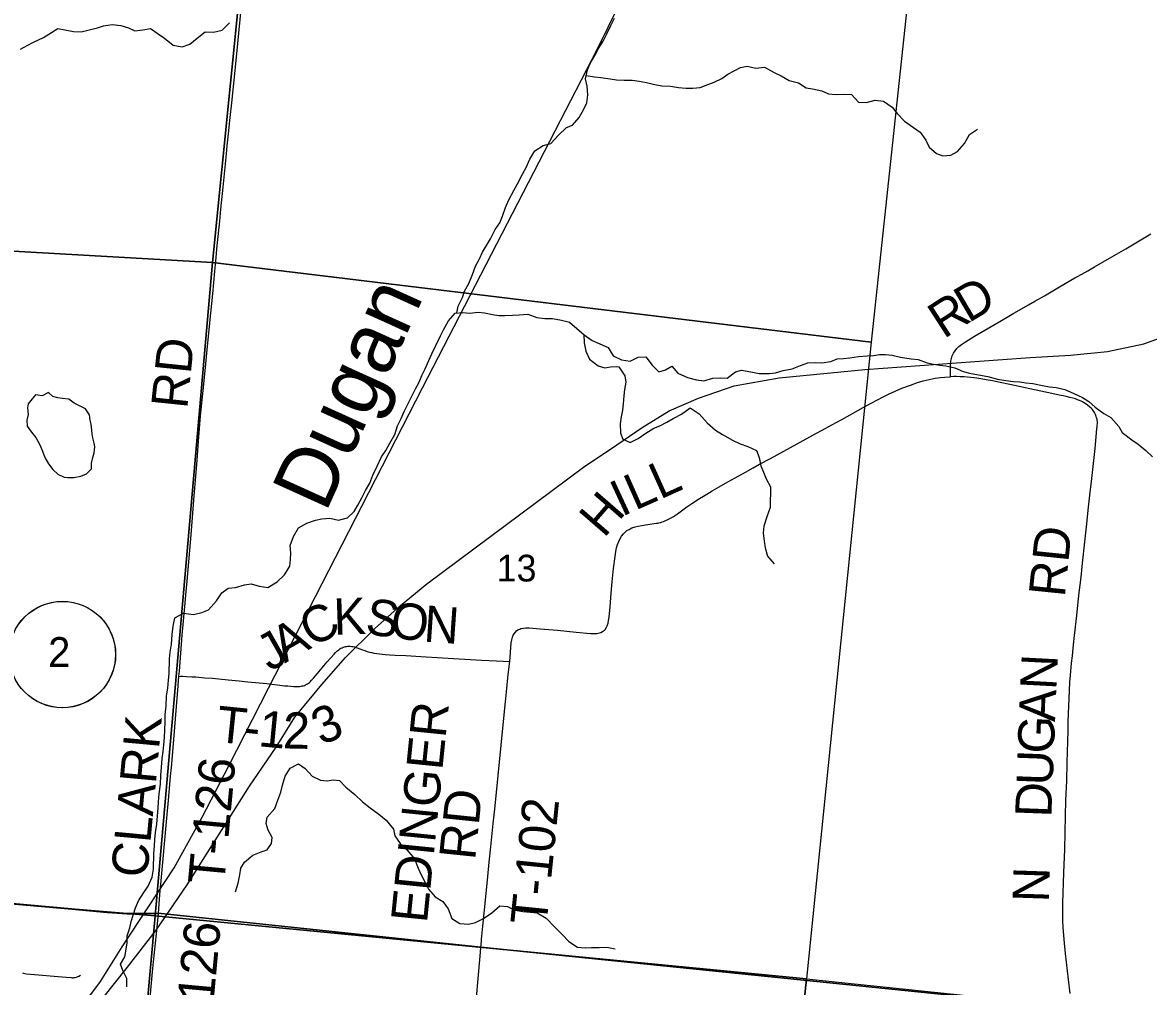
# Model space of a CAD drawing. Extents: x 0 to 1067, y 0 to 440.
# Drawn here: x 403.1 to 508.9, y 167.1 to 257.7 of the extents above; entities that cross this region are included whole.
import ezdxf

# ---------------------------------------------------------------- set-up
doc = ezdxf.new("R2010")
doc.units = 0
for name, color, linetype in [('GM_X_City_Street', 7, 'Continuous'), ('GM_X_Minor_Lake', 7, 'Continuous'), ('GM_X_Minor_River', 7, 'Continuous'), ('GM_X_Minor_River_Text', 7, 'Continuous'), ('GM_X_Rail_Line', 7, 'Continuous'), ('GM_X_Section', 7, 'Continuous'), ('GM_X_Section_Text', 7, 'Continuous'), ('GM_X_Township_Road', 7, 'Continuous'), ('GM_X_Township_Road_Text', 7, 'Continuous'), ('SH_Masking', 7, 'Continuous'), ('SH_Text', 7, 'Continuous')]:
    doc.layers.add(name, color=color, linetype=linetype)

msp = doc.modelspace()

# ---------------------------------------------------------------- linework, layer by layer
at = {"layer": 'GM_X_City_Street'}
msp.add_lwpolyline([(403.08, 168.37), (403.17, 168.35), (403.3, 168.31), (403.45, 168.29), (407.17, 167.97), (407.64, 167.93), (407.76, 167.92), (407.83, 167.92), (407.9, 167.93), (407.98, 167.94), (408.04, 167.95), (408.15, 167.98), (408.27, 168.02), (408.36, 168.05), (408.53, 168.15)], dxfattribs=at)
at = {"layer": 'GM_X_Minor_Lake'}
for points in [[(409.36, 215.55), (409.56, 215.75), (409.57, 216.27), (409.69, 216.79), (409.81, 217.25), (409.89, 217.79), (409.82, 218.14), (409.69, 218.66), (409.63, 219.03), (409.61, 219.37), (409.53, 219.94), (409.44, 220.31), (409.36, 220.81), (409, 221.36), (408.44, 221.64), (407.94, 221.9), (407.42, 222.29), (406.85, 222.33), (406.4, 222.4), (405.94, 222.52), (405.52, 222.91), (404.94, 222.58), (404.31, 222.7), (403.98, 222.32), (403.61, 221.84)], [(403.61, 221.84), (403.56, 221.46), (403.62, 220.84), (403.5, 220.3), (403.51, 219.75), (403.92, 219.17), (404.32, 218.67), (404.72, 218), (404.96, 217.38), (405.18, 216.81), (405.51, 216.21), (405.94, 215.68), (406.41, 215.24), (406.98, 214.96), (407.34, 214.91), (407.89, 214.93), (408.55, 215.05), (409.1, 215.27), (409.36, 215.55)]]:
    msp.add_lwpolyline(points, dxfattribs=at)
at = {"layer": 'GM_X_Minor_River'}
for points in [[(402.9, 255.18), (403.52, 255.51), (404.12, 255.82), (405.04, 256.26), (405.79, 256.73), (406.39, 257.11), (407.07, 256.99), (407.87, 256.82), (408.6, 256.81), (409.47, 257.02), (410.13, 257.17), (410.7, 257.37), (411.52, 257.5), (412.32, 257.4), (413.04, 257.16), (413.63, 256.9), (414.39, 257), (415.12, 257.11), (415.82, 256.6), (416.42, 256.2), (417.24, 255.53), (418.08, 255.38), (418.81, 255.64), (419.5, 256.2), (420.24, 256.79), (421.03, 256.78), (421.83, 256.95), (422.55, 257.64)], [(443.91, 230.38), (444.04, 231.03), (444.42, 231.82), (444.63, 232.43), (445.03, 233.16), (445.36, 233.99), (445.66, 234.77), (446.02, 235.47), (446.3, 236.08), (446.7, 236.73), (447.07, 237.34), (447.51, 238.23), (447.93, 238.84), (448.19, 239.49), (448.48, 240.29), (448.78, 241.01), (449.25, 241.9), (449.6, 242.51), (450.09, 243.43), (450.42, 244.05), (450.75, 244.82), (451.24, 245.61), (452.02, 246.12), (452.75, 246.29), (453.47, 247.1), (454.21, 247.82), (454.78, 248.02), (455.39, 248.74), (455.83, 249.53), (456.11, 250.12), (456.21, 250.89), (456.16, 251.69), (456.01, 252.38), (456.18, 253.24), (456.42, 253.83), (456.86, 254.56), (457.21, 255.23), (457.65, 255.91), (458, 256.61), (458.38, 257.38), (458.73, 258.08)], [(456.07, 252.69), (456.83, 252.57), (457.44, 252.52), (458.31, 252.37), (458.92, 252.29), (459.63, 252.26), (460.38, 252.25), (461.04, 252.15), (461.74, 252.03), (462.36, 251.88), (463.17, 251.73), (463.99, 251.68), (464.74, 251.58), (465.45, 251.5), (466.09, 251.51), (466.77, 251.57), (467.34, 251.79), (468.08, 252.08), (468.81, 252.41), (469.38, 252.81), (469.98, 253.12), (470.56, 253.46), (471.2, 253.58), (472.01, 253.37), (472.81, 253.49), (473.72, 252.98), (474.39, 252.67), (475.14, 252.23), (476.03, 252.01), (476.75, 251.53), (477.34, 251.43), (478.22, 251.25), (478.84, 250.97), (479.56, 250.92), (480.36, 250.95), (481, 250.9), (481.65, 250.18), (482.42, 250.15), (483.22, 250.39), (484.02, 250.29), (484.81, 249.73), (485.28, 249.13), (485.97, 248.41), (486.83, 247.81), (487.44, 247.37), (487.98, 246.61), (488.31, 245.97), (488.98, 245.36), (489.57, 245.15), (490.32, 245.21), (490.97, 245.56), (491.62, 246.31), (492.08, 247.14), (492.84, 247.64)], [(412.91, 171.16), (412.92, 171.85), (413.16, 172.6), (413.28, 173.21), (413.52, 173.89), (413.71, 174.48), (413.97, 175.14), (414.48, 175.91), (414.88, 176.52), (415.28, 177.38), (415.4, 178.13), (415.42, 179.59), (415.48, 180.32), (415.51, 180.89), (415.59, 181.55), (415.69, 182.34), (415.77, 183.14), (415.83, 183.84), (415.86, 184.46), (415.91, 185.21), (416.04, 186.1), (416.08, 186.92), (416.13, 187.69), (416.21, 188.53), (416.31, 189.17), (416.37, 189.81), (416.42, 190.49), (416.46, 191.2), (416.49, 191.93), (416.5, 192.63), (416.58, 193.48), (416.61, 194.39), (416.74, 195.14), (416.8, 195.89), (416.87, 196.46), (416.89, 197.87), (416.97, 198.51), (417.09, 199.26), (417.15, 200.17), (417.23, 200.94), (417.4, 201.74), (418.21, 202.16), (419.14, 202.06), (419.92, 202.23), (420.56, 202.49), (421.32, 203.33), (421.81, 204.09), (422.41, 204.52), (423.09, 204.6), (423.94, 204.82), (424.58, 204.94), (425.33, 204.71), (426.15, 204.58), (427, 205.12), (427.69, 205.77), (428.22, 206.6), (428.28, 207.22), (428.29, 207.81), (428.25, 208.52), (428.56, 209.38), (429.03, 210.19), (429.81, 210.62), (430.61, 210.9), (431.2, 211.05), (431.98, 211.11), (432.77, 210.9), (433.64, 211.13), (434.24, 211.72), (434.59, 212.33), (434.99, 213.08), (435.32, 213.69), (435.74, 214.39), (436, 215.14), (436.42, 216), (436.82, 216.86), (437.22, 217.47), (437.59, 218.15), (438.08, 218.96), (438.34, 219.78), (438.67, 220.48), (438.96, 221.11), (439.26, 221.75), (439.68, 222.56), (440.03, 223.26), (440.36, 223.88), (440.62, 224.49), (440.93, 225.14), (441.26, 225.91), (441.56, 226.55), (441.94, 227.32), (442.38, 228.22), (442.64, 228.81), (443.11, 229.63), (443.73, 230.37), (444.46, 230.43), (445.1, 230.35), (445.92, 230.45), (446.49, 230.4), (447.24, 230.25), (447.85, 230.13), (448.42, 230.15)], [(448.42, 230.15), (449.15, 230.18), (449.77, 230.22), (450.59, 230.28), (451.41, 229.97), (452.18, 229.85), (452.88, 229.86), (453.75, 229.69), (454.5, 229.52), (455.19, 228.92), (455.87, 228.34), (456.61, 227.8), (457.34, 227.47), (458.13, 227.14), (458.6, 226.34), (459.39, 225.99), (460.18, 225.84), (460.94, 226.24), (461.67, 226.25), (462.25, 225.47), (462.9, 224.84), (463.52, 225.04), (464.1, 225.37), (464.68, 224.71), (465.58, 224.33), (466.42, 224.09), (467.11, 224.01), (467.95, 224.25), (468.73, 224.29), (469.3, 224.26), (470.08, 224.86), (470.65, 225.01), (471.54, 224.86), (472.33, 224.69), (473.29, 224.7), (473.86, 224.76), (474.59, 224.96), (475.41, 225.13), (476.19, 225.46), (476.9, 225.7), (477.59, 225.74), (478.22, 225.68), (479.07, 225.83), (479.64, 226.07), (480.26, 226.11), (480.83, 226.17), (481.65, 226.3), (482.49, 226.35), (483.06, 226.39), (483.63, 226.48), (484.2, 226.49), (484.82, 226.41), (485.61, 226.22), (486.61, 226.07), (487.27, 226.02), (488.11, 225.68), (488.72, 225.56), (489.31, 225.49), (489.88, 225.41), (490.7, 225.24), (491.49, 224.89), (492.08, 224.74), (492.92, 224.57), (493.81, 224.4), (494.72, 224.16), (495.49, 224.03), (496.24, 223.95), (496.81, 223.9), (497.4, 223.82), (498.04, 223.75), (498.95, 223.58), (499.6, 223.43), (500.22, 223.38), (501.06, 223.2), (501.83, 222.85), (502.71, 222.43), (503.3, 222.06), (503.91, 221.52), (504.72, 220.94), (505.37, 220.55), (506.13, 219.72), (506.45, 219.14), (507.35, 218.45), (507.93, 218.05), (508.65, 217.45), (509.28, 216.85)], [(455.85, 228.36), (455.86, 227.58), (456.03, 226.78), (456.36, 226.05), (457.19, 225.4), (457.81, 225.23), (458.52, 225.36), (459.13, 225.31), (459.69, 224.48), (459.79, 223.88), (459.65, 223.18), (459.61, 222.59), (459.54, 221.84), (459.46, 221.24), (459.34, 220.61), (459.26, 219.95), (459.29, 219.1), (459.51, 218.51), (460.21, 218.2), (460.95, 218.6), (461.68, 219.09), (462.42, 219.56), (462.99, 219.78), (463.63, 220.12), (464.23, 220.45), (465.03, 220.87), (465.84, 221.48), (466.67, 220.9), (467.44, 220.06), (468.2, 219.37), (468.88, 218.97), (469.81, 218.44), (470.53, 218.08), (471.26, 217.82), (472.07, 217.45), (472.33, 216.81), (472.48, 216.01), (472.72, 215.41), (472.99, 214.81), (473.37, 214.03), (473.38, 213.44), (473.35, 212.74), (473.36, 212.1), (473.03, 211.21), (472.77, 210.35), (472.69, 209.71), (472.79, 208.94), (472.87, 208.32), (473.09, 207.54), (473.74, 206.8)], [(423.1, 176), (423.36, 176.79), (423.51, 177.59), (423.61, 178.2), (423.96, 178.79), (424.74, 179.42), (425.5, 179.75), (426.07, 179.94), (426.49, 180.53), (426.54, 181.1), (426.18, 181.79), (425.97, 182.41), (426.09, 183), (426.81, 183.81), (427.07, 184.6), (427.37, 185.35), (427.52, 186.01), (427.76, 186.85), (428.23, 187.6), (429.01, 188), (429.66, 187.58), (430.31, 186.86), (431.08, 186.49), (431.7, 186.43), (432.29, 186.51), (432.88, 186.44), (433.46, 185.82), (434.3, 185.14), (435.02, 184.45), (435.76, 183.87), (436.57, 183.29), (437.27, 182.71), (437.96, 181.88), (438.07, 181.26), (438.58, 180.53), (439.23, 179.9), (439.93, 179.09), (440.28, 178.22), (440.54, 177.6), (440.94, 176.87), (441.25, 176.23), (441.86, 175.51), (442.6, 175.07), (443.1, 174.38), (443.42, 173.49), (444.19, 173.02), (445.01, 172.96), (445.65, 173.11), (446.41, 173.47), (447.19, 174.03), (447.93, 174.68), (448.66, 174.6), (449.38, 174.27), (450.11, 174.15), (450.81, 174.09), (451.45, 174.01), (452.29, 173.5), (453.16, 172.65), (453.79, 171.98), (454.44, 171.31), (455.25, 170.79), (455.98, 170.72), (456.55, 170.75), (457.28, 170.77), (457.99, 170.78), (458.78, 170.63)], [(412.89, 167.06), (412.87, 167.85), (412.5, 168.61), (412.3, 169.18), (412.69, 169.88), (412.91, 171.16)]]:
    msp.add_lwpolyline(points, dxfattribs=at)
at = {"layer": 'GM_X_Rail_Line'}
for points in [[(408.56, 165.1), (410.41, 167.56), (412.44, 170.81), (417.32, 178.23), (419.98, 182.99), (422.46, 187.82), (426.2, 195.11), (440.66, 223.35), (457.12, 255.21), (463.1, 267.38), (466.12, 273.22), (468.95, 277.71), (472.1, 282.34), (474.93, 286.23), (477.92, 290.37), (491.28, 306.36), (506.27, 324.25), (534.38, 357.19), (539, 362.72)], [(409.52, 164.62), (412.95, 168.92), (415.65, 172.39), (418.55, 176.66), (424.42, 185.93), (426.91, 189.58), (428.68, 192.4), (431.2, 195.48), (433.45, 198.02), (436.16, 200.71), (438.6, 202.89), (441.08, 204.93), (455.8, 215.89), (458.95, 218), (461.32, 219.62), (463.86, 221.17), (466.61, 222.36), (469.96, 223.52), (474.2, 224.3), (482.24, 225.06), (492.58, 225.83), (497.8, 226.21), (501.58, 226.41), (505.06, 226.77), (508.48, 227.47), (511.67, 228.63)]]:
    msp.add_lwpolyline(points, dxfattribs=at)
at = {"layer": 'GM_X_Section'}
for points in [[(365.53, 299.9), (426.84, 293.81), (420.94, 235.13), (359.76, 238.61)], [(489.23, 287.4), (482.85, 227.63), (420.94, 235.13), (426.84, 293.81)], [(359.76, 238.61), (420.94, 235.13), (415.56, 173.73), (353.18, 178.94)], [(482.85, 227.63), (476.78, 167.81), (415.56, 173.73), (420.94, 235.13)], [(353.18, 178.94), (415.56, 173.73), (410.18, 114.4), (348.26, 119.58)], [(476.78, 167.81), (470.49, 107.7), (410.18, 114.4), (415.56, 173.73)], [(537.23, 161.53), (531.15, 101.7), (501.28, 103.8), (470.49, 107.7), (476.78, 167.81)]]:
    msp.add_lwpolyline(points, close=True, dxfattribs=at)
at = {"layer": 'GM_X_Township_Road'}
for points in [[(421.25, 235.26), (421.39, 236.71), (421.62, 239), (421.73, 240.12), (421.94, 242.2), (422.24, 245.32), (422.32, 246.1), (422.44, 247.21), (422.61, 248.76), (422.76, 250.13), (422.89, 251.36), (423.07, 253.18), (423.31, 255.7), (423.63, 258.93)], [(490.29, 224.39), (490.29, 225.28), (490.3, 225.55), (490.34, 225.85), (490.4, 226.11), (490.47, 226.36), (490.58, 226.61), (490.73, 226.83), (490.9, 227.04), (491.1, 227.22), (491.33, 227.42), (491.7, 227.67), (492.56, 228.2), (495.11, 229.67), (495.79, 230.07), (496.27, 230.35), (497.65, 231.16), (498.24, 231.48), (499.14, 232), (500.72, 232.92), (502, 233.68), (502.19, 233.79), (502.65, 234.04), (503.2, 234.35), (503.85, 234.71), (505.46, 235.65), (506.78, 236.42), (507.87, 237.06), (509.12, 237.81)], [(417.78, 196.23), (417.82, 196.73), (417.96, 198.41), (418.1, 200.11), (418.34, 202.79), (418.47, 204.22), (418.56, 205.19), (418.65, 206.27), (418.92, 209.54), (419.22, 213.21), (419.37, 215.02), (419.49, 216.56), (419.63, 218.35), (419.82, 220.7), (420.07, 223.09), (420.26, 224.95), (420.48, 227.25), (420.79, 230.36), (420.96, 232.18), (421.16, 234.3), (421.25, 235.26)], [(448.87, 197.63), (448.95, 198.47), (449.02, 199.37), (449.07, 199.67), (449.13, 199.93), (449.21, 200.11), (449.29, 200.24), (449.41, 200.4), (449.52, 200.5), (449.65, 200.6), (449.82, 200.68), (449.93, 200.72), (450.16, 200.77), (450.39, 200.79), (450.69, 200.78), (451.73, 200.7), (453.37, 200.56), (455.11, 200.39), (456.48, 200.27), (456.78, 200.25), (457.07, 200.26), (457.32, 200.31), (457.45, 200.36), (457.6, 200.45), (457.77, 200.58), (457.84, 200.65), (457.98, 200.86), (458.04, 200.99), (458.12, 201.23), (458.17, 201.48), (458.21, 201.81), (458.31, 202.77), (458.42, 204.04), (458.51, 205.11), (458.64, 206.38), (458.77, 207.49), (458.84, 207.97), (458.91, 208.3), (459.01, 208.63), (459.12, 208.91), (459.25, 209.19), (459.39, 209.41), (459.56, 209.62), (459.71, 209.79), (459.89, 209.93), (460.09, 210.05), (460.36, 210.18), (460.68, 210.3), (460.94, 210.36), (461.64, 210.47), (462.67, 210.62), (462.81, 210.64), (462.88, 210.65), (463.01, 210.68), (463.08, 210.7), (463.21, 210.75), (463.34, 210.79), (463.67, 210.93), (464, 211.09), (464.28, 211.27), (464.64, 211.52), (464.88, 211.7), (465.51, 212.16), (465.98, 212.48), (466.7, 212.94), (467.08, 213.17), (467.4, 213.36), (467.91, 213.67), (468.55, 214.05), (469.36, 214.52), (470.05, 214.89), (471.02, 215.43), (471.74, 215.82), (472.36, 216.16), (473.37, 216.71), (474.65, 217.4), (475.9, 218.07), (477.65, 219.05), (478.25, 219.37), (479.16, 219.86), (480.08, 220.37), (481.37, 221.1), (482.32, 221.62), (483.97, 222.49), (484.47, 222.74), (485.74, 223.3), (486.54, 223.61), (487.21, 223.84), (487.75, 224), (488.3, 224.13), (488.85, 224.24), (489.37, 224.31), (489.77, 224.35), (490.29, 224.39)], [(501.54, 166.42), (501.38, 167.76), (501.11, 170.2), (501.02, 171.17), (500.95, 171.87), (500.89, 172.66), (500.86, 173.25), (500.85, 173.89), (500.86, 174.93), (500.96, 177.8), (501.01, 179.26), (501.04, 179.96), (501.09, 181.6), (501.11, 183.09), (501.15, 184.59), (501.23, 186.41), (501.27, 188.12), (501.3, 189.17), (501.32, 190.06), (501.35, 191.18), (501.37, 191.96), (501.39, 192.74), (501.45, 194.16), (501.53, 195.68), (501.58, 196.35), (501.68, 197.47), (501.76, 198.17), (501.87, 199.21), (501.96, 200.06), (502.17, 201.95), (502.28, 202.91), (502.41, 204.1), (502.57, 205.55), (502.71, 206.88), (502.93, 208.88), (503.08, 210.29), (503.27, 212.14), (503.4, 213.25), (503.55, 214.55), (503.89, 217.66), (504.07, 219.48), (504.09, 219.7), (504.1, 219.84), (504.11, 219.96), (504.11, 220.07), (504.11, 220.13), (504.11, 220.19), (504.1, 220.25), (504.09, 220.32), (504.08, 220.38), (504.06, 220.45), (504.03, 220.54), (504, 220.64), (503.92, 220.84), (503.83, 221.04), (503.7, 221.22), (503.61, 221.33), (503.51, 221.43), (503.39, 221.54), (503.17, 221.73), (503.06, 221.8), (502.81, 221.96), (502.71, 222.02), (502.59, 222.09), (502.43, 222.16), (502.24, 222.23), (502.04, 222.3), (501.79, 222.37), (501.52, 222.44), (501.18, 222.52), (500.88, 222.58), (500.51, 222.66), (499.83, 222.81), (497.76, 223.25), (496.76, 223.46), (495.89, 223.65), (494.97, 223.84), (494.25, 223.99), (493.65, 224.1), (493.17, 224.18), (492.77, 224.25), (492.23, 224.32), (491.86, 224.35), (491.58, 224.37), (491.22, 224.39), (490.87, 224.4), (490.61, 224.4), (490.29, 224.39)], [(417.78, 196.23), (417.94, 196.24), (418.14, 196.24), (418.49, 196.23), (418.98, 196.2), (419.38, 196.18), (420.22, 196.11), (420.95, 196.05), (422.41, 195.9), (423.45, 195.8), (424.27, 195.73), (426.05, 195.55), (427.72, 195.36), (428.01, 195.34), (428.31, 195.31), (428.58, 195.29), (428.79, 195.28), (428.92, 195.28), (429.04, 195.28), (429.16, 195.29), (429.26, 195.31), (429.37, 195.33), (429.48, 195.36), (429.58, 195.39), (429.67, 195.43), (429.78, 195.49), (429.86, 195.54), (429.96, 195.6), (430.04, 195.66), (430.14, 195.76), (430.22, 195.84), (430.42, 196.07), (430.61, 196.28), (431.72, 197.6), (432.36, 198.32), (432.51, 198.48), (432.63, 198.59), (432.72, 198.67), (432.81, 198.74), (432.9, 198.81), (433, 198.87), (433.11, 198.92), (433.21, 198.97), (433.33, 199.01), (433.44, 199.03), (433.55, 199.05), (433.66, 199.06), (433.76, 199.07), (433.89, 199.07), (434.01, 199.05), (434.08, 199.05), (434.15, 199.03), (434.27, 199), (434.52, 198.91), (434.77, 198.82), (435.04, 198.72), (435.26, 198.65), (435.46, 198.58), (435.68, 198.52), (435.9, 198.47), (436.11, 198.42), (436.39, 198.38), (436.66, 198.34), (436.88, 198.31), (437.18, 198.29), (437.61, 198.26), (438.11, 198.23), (439.12, 198.18), (440.53, 198.11), (442.54, 197.98), (446.22, 197.75), (447.63, 197.68), (448.87, 197.63)], [(446.23, 171.52), (446.35, 172.75), (446.47, 173.97), (446.63, 175.53), (446.81, 177.42), (446.95, 178.79), (447.11, 180.23), (447.33, 182.42), (447.46, 183.76), (447.79, 186.91), (448.36, 192.62), (448.48, 193.84), (448.57, 194.77), (448.74, 196.4), (448.87, 197.63)], [(415.85, 173.95), (416, 175.74), (416.1, 177.03), (416.6, 182.55), (416.82, 184.96), (417, 186.85), (417.08, 187.67), (417.23, 189.52), (417.46, 192.24), (417.68, 194.95), (417.78, 196.23)], [(400.34, 175.05), (407.69, 174.39), (411.03, 174.09), (412, 174.01), (412.89, 173.95), (412.96, 173.95), (413.19, 173.94), (413.45, 173.94), (413.74, 173.94), (414.49, 173.96), (415.84, 173.98), (446.16, 170.8), (501.66, 165.12)], [(501.66, 165.12), (446.16, 170.8), (415.84, 173.98), (414.49, 173.96), (413.74, 173.94), (413.45, 173.94), (413.19, 173.94), (412.96, 173.95), (412.89, 173.95), (412, 174.01), (411.03, 174.09), (407.69, 174.39), (400.34, 175.05)], [(400.53, 175), (407.71, 174.35), (411.05, 174.06), (412.01, 173.97), (412.9, 173.92), (412.97, 173.92), (413.2, 173.91), (413.46, 173.9), (413.76, 173.91), (414.5, 173.93), (415.85, 173.95)], [(415.4, 169.41), (415.67, 172.04), (415.85, 173.95)], [(446.17, 170.77), (446.22, 171.34), (446.23, 171.52)], [(445.66, 165.01), (445.74, 166.03), (445.91, 167.85), (446.1, 169.93), (446.17, 170.77)], [(414.68, 161.57), (414.69, 161.63), (415, 165.07), (415.14, 166.74), (415.3, 168.48), (415.4, 169.41)]]:
    msp.add_lwpolyline(points, dxfattribs=at)
at = {"layer": 'SH_Masking'}
msp.add_circle((406.83, 198.28), 5, dxfattribs=at)
at = {"layer": 'SH_Text'}
msp.add_circle((406.82, 198.29), 5, dxfattribs=at)

# ---------------------------------------------------------------- texts
at = {"layer": 'GM_X_Minor_River_Text'}
msp.add_text('Dugan', height=5.681, rotation=65.6144, dxfattribs=at).set_placement((431.56, 211.52))
at = {"layer": 'GM_X_Section_Text'}
msp.add_text('13', height=2.511, rotation=0, dxfattribs=at).set_placement((447.65, 205.15))
at = {"layer": 'GM_X_Township_Road_Text'}
for s, height, rotation, p in [('D', 3.41, 30.5546, (491.99, 229.4)), ('R', 3.41, 32.9756, (489.67, 227.9)), ('RD', 3.409, 84.0934, (418.55, 221.31)), ('L', 3.41, 24.2747, (463, 212.83)), ('L', 3.41, 23.9442, (460.65, 211.79)), ('I', 3.41, 24.8613, (459.39, 211.2)), ('H', 3.41, 49.1095, (457.73, 209.16)), ('RD', 3.409, 84.1435, (501.04, 203.61)), ('K', 3.41, 1.9419, (432.36, 200.13)), ('S', 3.41, 351.9532, (435.21, 200.24)), ('O', 3.41, 352.6547, (437.53, 199.91)), ('C', 3.41, 28.4662, (430.3, 198.9)), ('N', 3.41, 356.0102, (440.72, 199.51)), ('A', 3.41, 29.5939, (427.71, 197.43)), ('J', 3.41, 29.5814, (426.32, 196.64)), ('N', 3.41, 86.9933, (500.24, 194.92)), ('A', 3.41, 87.8063, (500.13, 191.93)), ('T', 3.41, 354.1312, (421.21, 190.09)), ('1', 3.41, 354.5505, (425.17, 189.68)), ('2', 3.41, 358.7944, (427.53, 189.47)), ('3', 3.41, 22.925, (431.16, 189.72)), ('EDINGER', 3.409, 84.2589, (441.09, 172.99)), ('CLARK', 3.409, 84.7322, (414.79, 177.24)), ('G', 3.41, 87.8065, (500.01, 188.93)), ('-', 3.41, 354.2055, (423.75, 189.83)), ('T-126', 3.409, 84.6813, (422.02, 176.59)), ('U', 3.41, 87.8101, (499.9, 185.94)), ('RD', 3.409, 84.0953, (445.62, 178.91)), ('D', 3.41, 87.8065, (499.78, 182.94)), ('T-102', 3.409, 84.1839, (452.32, 172.77)), ('N', 3.41, 88.1232, (499.54, 174.97)), ('T-126', 3.409, 84.7298, (420.63, 161.19))]:
    msp.add_text(s, height=height, rotation=rotation, dxfattribs=at).set_placement(p)
at = {"layer": 'SH_Text'}
msp.add_text('2', height=2.8, rotation=360, dxfattribs=at).set_placement((405.49, 197.12))

doc.saveas('drawing.dxf')
